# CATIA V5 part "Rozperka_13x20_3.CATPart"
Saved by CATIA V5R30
Part number: Rozperka_13x20_3
Definition: ISO 13337-13x20
Nomenclature: ISO 13337-13x20
Source: Unknown
Description: PART--DESC
Bounding box of the stored display mesh (mm): x 123 to 135.975, y 12.006 to 24.994, z 29.7 to 49.7
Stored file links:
  E:\Bakalarka\Model\Forma_v7\Rozperka_13x20_3.CATPart
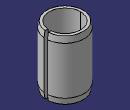
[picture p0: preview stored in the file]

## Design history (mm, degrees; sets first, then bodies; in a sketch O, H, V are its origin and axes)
Body1 "MANIFOLD_SOLID_BREP #3698" (main body)
  Solid1: solid without history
